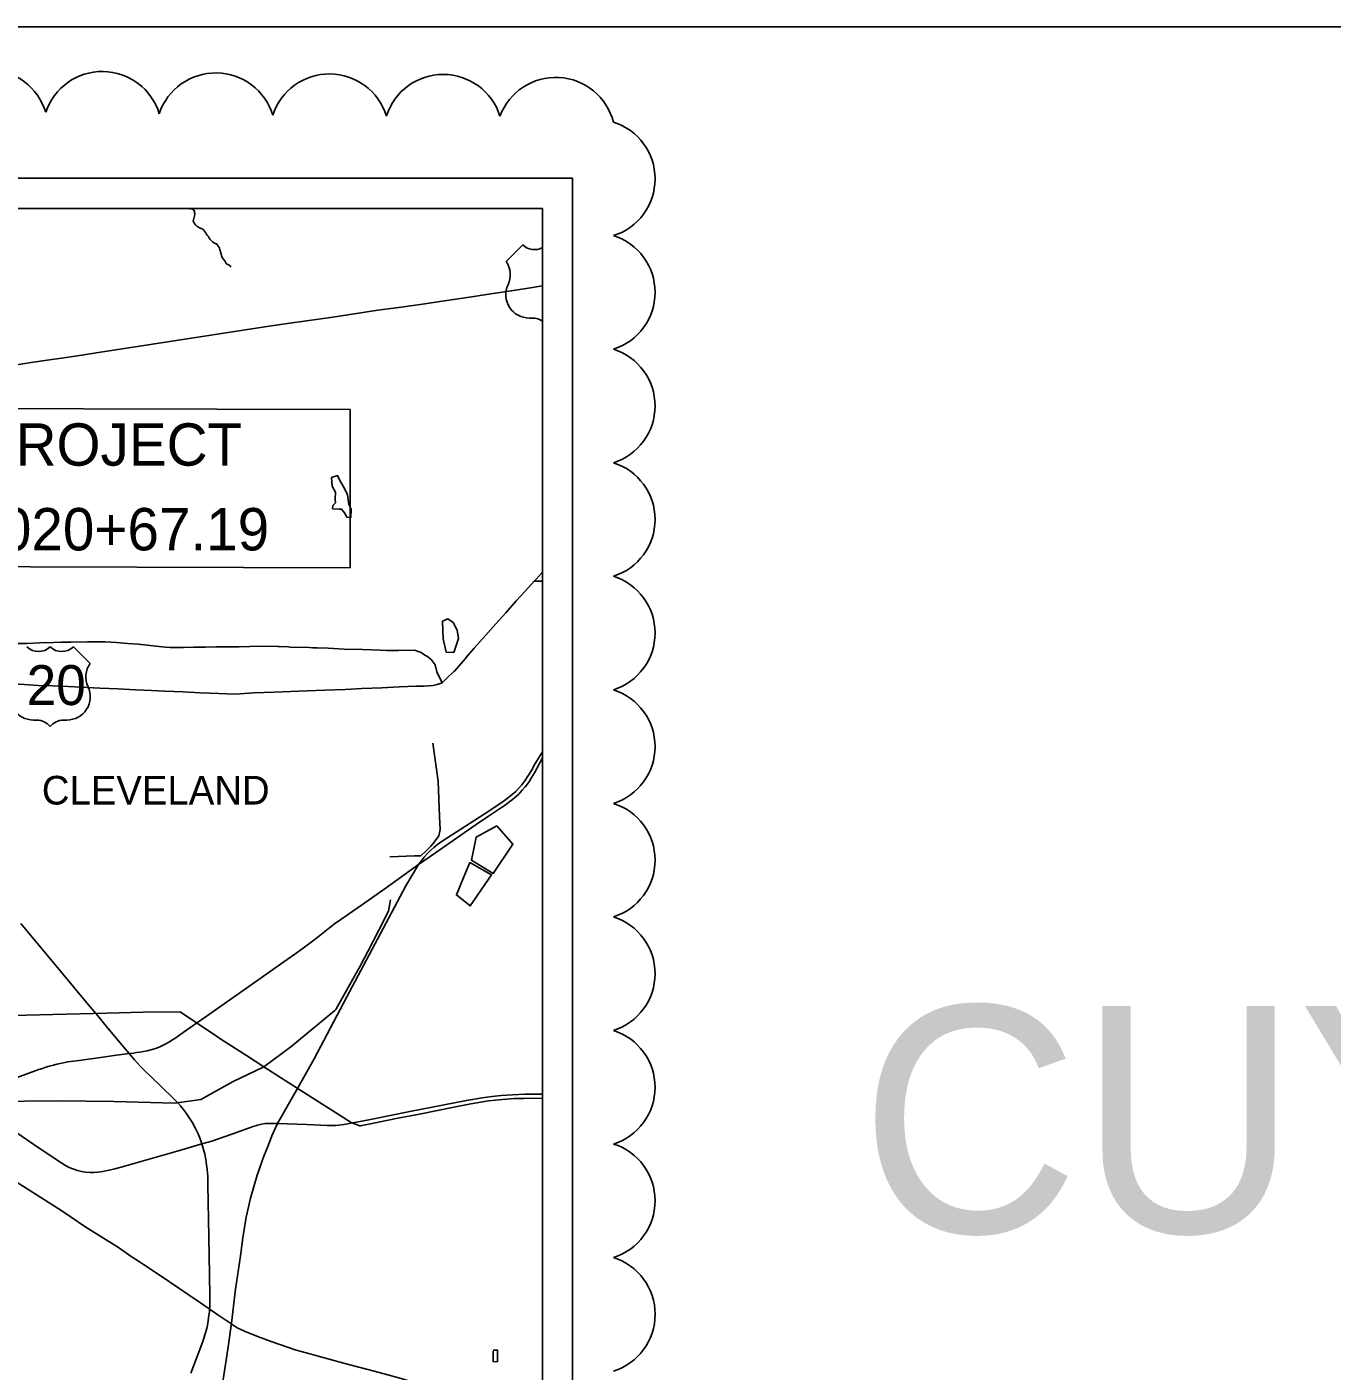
# Model space of a CAD drawing. Extents: x 0 to 96.2, y -27.5 to 31.3.
# Drawn here: x 48.919 to 53.234, y 16.942 to 21.387 of the extents above; entities that cross this region are included whole.
import ezdxf

# ---------------------------------------------------------------- set-up
doc = ezdxf.new("R2010")
doc.units = 0
for name, color, linetype in [('BOTTOM-BLKS', 7, 'Continuous'), ('DIM', 7, 'Continuous'), ('TB1', 7, 'Continuous'), ('TB_BORDER', 7, 'Continuous'), ('TB_PP_50x10', 7, 'Continuous'), ('TB_PP_50x10_GRID', 7, 'Continuous'), ('TB_PROF_30x10_GRID', 7, 'Continuous'), ('TB_PSDSOD', 7, 'Continuous'), ('TB_SIGN_XS', 7, 'Continuous'), ('TB_SUPER_50x0-5', 7, 'Continuous'), ('TB_SUPER_50x1', 7, 'Continuous'), ('TB_SUPER_50x1_GRID', 7, 'Continuous'), ('TB_UNDERDRAIN', 7, 'Continuous')]:
    doc.layers.add(name, color=color, linetype=linetype)

msp = doc.modelspace()

# ---------------------------------------------------------------- linework, layer by layer
at = {"layer": 'BOTTOM-BLKS'}
msp.add_lwpolyline([(43.8234, 18.3711), (43.8234, 13.9869), (50.6234, 13.9869), (50.6234, 20.7869), (47.5697, 20.7869)], dxfattribs=at)
at = {"layer": 'DIM'}
msp.add_lwpolyline([(43.2234, 21.3869), (74.7234, 21.3869), (74.7234, 0.3869), (43.2234, 0.3869)], close=True, dxfattribs=at)
at = {"layer": 'TB1'}
for p, q in [((43.7234, 20.8869), (50.7234, 20.8869)), ((50.7234, 20.8869), (50.7234, 13.8869)), ((43.8234, 20.7869), (50.6234, 20.7869)), ((50.6234, 20.7869), (50.6234, 13.9869))]:
    msp.add_line(p, q, dxfattribs=at)
at = {"layer": 'TB_BORDER'}
msp.add_lwpolyline([(49.4466, 20.7869), (49.4479, 20.7863), (49.4506, 20.7859), (49.4578, 20.7857), (49.4635, 20.7858), (49.4654, 20.7858), (49.4669, 20.7839), (49.4688, 20.7832), (49.4712, 20.7806), (49.4727, 20.7772), (49.4728, 20.7753), (49.4732, 20.7726), (49.474, 20.7688), (49.4748, 20.7669), (49.4737, 20.7623), (49.4719, 20.7577), (49.4705, 20.7528), (49.4694, 20.749), (49.469, 20.7471), (49.4691, 20.7448), (49.471, 20.741), (49.4737, 20.7369), (49.4765, 20.7323), (49.4788, 20.7305), (49.4811, 20.7282), (49.4834, 20.7267), (49.4865, 20.7249), (49.4903, 20.723), (49.4987, 20.7194), (49.5006, 20.7179), (49.5026, 20.7156), (49.5065, 20.7111), (49.5096, 20.707), (49.5123, 20.7028), (49.5154, 20.6983), (49.5181, 20.6946), (49.5205, 20.6908), (49.522, 20.6882), (49.5236, 20.6859), (49.5251, 20.684), (49.529, 20.6795), (49.5328, 20.6762), (49.5355, 20.6743), (49.5375, 20.6728), (49.5401, 20.6713), (49.5436, 20.6699), (49.5466, 20.6691), (49.5494, 20.6654), (49.5517, 20.6624), (49.5536, 20.6601), (49.5556, 20.6552), (49.5572, 20.6499), (49.5588, 20.6438), (49.5604, 20.6389), (49.5612, 20.6355), (49.562, 20.6332), (49.5628, 20.6302), (49.5636, 20.6279), (49.5652, 20.6249), (49.5679, 20.6204), (49.573, 20.6129), (49.5742, 20.611), (49.5753, 20.6087), (49.5769, 20.6065), (49.5784, 20.6046), (49.58, 20.6027), (49.5834, 20.6012), (49.5857, 20.5998), (49.5888, 20.5979), (49.5942, 20.5936)], dxfattribs=at)
at = {"layer": 'TB_PP_50x10_GRID'}
for points in [[(50.2136, 18.6169), (50.2181, 18.6233), (50.2251, 18.6322), (50.2323, 18.6415), (50.2426, 18.6523), (50.2542, 18.6642), (50.2644, 18.6733), (50.2769, 18.6833), (50.2919, 18.6943), (50.4304, 18.7837), (50.4859, 18.8201), (50.5066, 18.8351), (50.5243, 18.8494), (50.535, 18.8588), (50.5443, 18.8686), (50.555, 18.8808), (50.5655, 18.8945), (50.5756, 18.9094), (50.5871, 18.9284), (50.5999, 18.9515), (50.6234, 18.9902)], [(50.2136, 18.6169), (50.2705, 18.6556), (50.3649, 18.722), (50.4045, 18.7496), (50.4451, 18.7775), (50.4879, 18.8053), (50.5004, 18.8139), (50.5117, 18.8219), (50.5202, 18.8284), (50.5298, 18.8362), (50.5379, 18.8436), (50.5453, 18.8504), (50.5569, 18.8627), (50.5663, 18.8738), (50.5731, 18.8822), (50.5802, 18.8926), (50.5864, 18.9025), (50.592, 18.9117), (50.5971, 18.9207), (50.6234, 18.97)], [(49.2578, 17.9919), (49.2711, 17.9937), (49.2818, 17.9952), (49.2924, 17.9969), (49.3041, 17.9988), (49.3169, 18.0014), (49.3286, 18.0044), (49.3406, 18.0079), (49.3508, 18.0116), (49.3634, 18.0168), (49.3759, 18.0228), (49.3881, 18.0295), (49.4004, 18.0372), (49.411, 18.0441), (49.4247, 18.0539), (49.4579, 18.0771), (49.5085, 18.1125), (49.6008, 18.1772), (49.6822, 18.2344), (49.7685, 18.2951), (49.8054, 18.321), (49.833, 18.3408), (49.8549, 18.3573), (49.8673, 18.3666), (49.8823, 18.3787), (49.9151, 18.4046), (49.9364, 18.4207), (49.957, 18.4354), (49.9824, 18.4533), (50.0249, 18.4831), (50.099, 18.535), (50.2136, 18.6169)], [(49.7478, 17.7613), (49.8147, 17.8786), (49.8688, 17.9749), (49.977, 18.1803), (50.1154, 18.4408), (50.1723, 18.5472), (50.2136, 18.6169)], [(48.8989, 18.4225), (49.0301, 18.2651), (49.116, 18.1615), (49.1534, 18.1165), (49.187, 18.0766), (49.2389, 18.0141), (49.2578, 17.9919)], [(48.321, 17.6924), (48.5615, 17.7814), (48.6387, 17.8158), (48.7384, 17.8526), (48.7641, 17.8612), (48.7995, 17.8782), (48.8425, 17.897), (48.8963, 17.9164), (48.9462, 17.9349), (48.9581, 17.939), (48.9707, 17.9432), (48.9821, 17.9469), (48.9938, 17.9505), (49.0068, 17.9538), (49.0185, 17.957), (49.0407, 17.9615), (49.0549, 17.9643), (49.092, 17.9697), (49.1628, 17.9795), (49.2154, 17.9866), (49.2578, 17.9919)], [(49.2578, 17.9919), (49.2753, 17.9716), (49.2952, 17.9494), (49.312, 17.9323), (49.3274, 17.9172), (49.3627, 17.8834), (49.4048, 17.8428), (49.4171, 17.8306), (49.4266, 17.8195), (49.436, 17.8082), (49.4456, 17.7954), (49.4548, 17.7823), (49.465, 17.7658), (49.4764, 17.7447), (49.4849, 17.7272), (49.4915, 17.7107), (49.498, 17.6935)], [(50.6234, 17.8582), (50.6179, 17.8582), (50.5655, 17.8577), (50.524, 17.856), (50.4867, 17.8535), (50.4572, 17.8506), (50.4244, 17.8462), (50.3722, 17.8375), (50.2981, 17.8225), (50.1855, 17.8003), (50.0554, 17.7744), (49.9798, 17.7593), (49.9674, 17.7573), (49.9507, 17.7551), (49.94, 17.7542), (49.9263, 17.7542), (49.912, 17.7542), (49.845, 17.7571), (49.7478, 17.7613)], [(49.7478, 17.7613), (49.7247, 17.7612), (49.7067, 17.7604), (49.6951, 17.7586), (49.6813, 17.7554), (49.6671, 17.7514), (49.6368, 17.7405), (49.6032, 17.7283), (49.568, 17.7155), (49.5465, 17.7077), (49.5309, 17.7027), (49.498, 17.6935)], [(49.5954, 17.1006), (49.6084, 17.2128), (49.6258, 17.3238), (49.6332, 17.3834), (49.6442, 17.4513), (49.6579, 17.5145), (49.6809, 17.5906), (49.7019, 17.653), (49.7175, 17.6906), (49.7285, 17.72), (49.7478, 17.7613)], [(49.498, 17.6935), (49.4316, 17.6744), (49.2307, 17.6163), (49.2102, 17.6107), (49.1912, 17.6064), (49.1698, 17.6024), (49.1541, 17.6001), (49.1399, 17.5992), (49.1281, 17.5992), (49.1133, 17.6004), (49.0998, 17.6025), (49.086, 17.6059), (49.0713, 17.6108), (49.0593, 17.6156), (49.0469, 17.6218), (49.0342, 17.6295), (48.9992, 17.653), (48.9418, 17.6919), (48.8855, 17.7301)], [(49.498, 17.6935), (49.502, 17.6785), (49.5069, 17.659), (49.5102, 17.6422), (49.513, 17.6241), (49.515, 17.6086), (49.517, 17.5863), (49.5177, 17.5587), (49.5201, 17.3849), (49.5223, 17.2604), (49.5237, 17.1885), (49.5237, 17.1614), (49.5225, 17.1397), (49.5199, 17.1185), (49.5168, 17.0991), (49.5136, 17.0829), (49.5078, 17.0623), (49.5019, 17.0431), (49.4944, 17.0226), (49.4818, 16.9902), (49.4608, 16.9356)], [(49.6742, 15.7073), (49.6719, 15.7355), (49.6647, 15.7911), (49.654, 15.8647), (49.6481, 15.9142), (49.6185, 16.1187), (49.5828, 16.3874), (49.5736, 16.447), (49.5653, 16.5012), (49.5553, 16.5644), (49.5516, 16.6213), (49.5507, 16.6727), (49.5534, 16.7295), (49.5553, 16.78), (49.5608, 16.8506), (49.5681, 16.9148), (49.5837, 17.0147), (49.5954, 17.1006)]]:
    msp.add_lwpolyline(points, dxfattribs=at)
at = {"layer": 'TB_PROF_30x10_GRID'}
for points in [[(50.119, 18.6432), (50.2002, 18.6456), (50.2217, 18.646), (50.2402, 18.664), (50.2543, 18.6777), (50.2624, 18.6873), (50.2689, 18.6955), (50.2806, 18.7125), (50.2852, 18.7334), (50.2832, 18.7758), (50.2786, 18.8933), (50.2612, 19.0184)], [(48.7979, 17.8332), (49.0235, 17.8357), (49.2068, 17.8333), (49.4078, 17.8283), (49.4946, 17.8407), (49.6012, 17.9002), (49.7004, 17.9473), (49.7024, 17.9487), (49.7922, 18.0142), (49.937, 18.1349), (49.9409, 18.1382), (50.0222, 18.2836), (50.0467, 18.3302), (50.0831, 18.4002), (50.1145, 18.463), (50.1211, 18.5004)]]:
    msp.add_lwpolyline(points, dxfattribs=at)
at = {"layer": 'TB_PSDSOD'}
for points in [[(48.2359, 18.1025), (48.8731, 18.1185), (49.1821, 18.1253), (49.3037, 18.129), (49.4261, 18.1302)], [(49.4261, 18.1302), (49.546, 18.0495), (49.5602, 18.0403)], [(49.5602, 18.0403), (49.645, 17.9856), (49.7024, 17.9487), (49.8126, 17.878), (49.9914, 17.7643), (50.0197, 17.7535)], [(50.0197, 17.7535), (50.0212, 17.7529), (50.0441, 17.7578), (50.145, 17.7781), (50.217, 17.7921), (50.3302, 17.8147), (50.3868, 17.8264), (50.4457, 17.8358), (50.4909, 17.8404), (50.5297, 17.8435), (50.5618, 17.8441), (50.6234, 17.8442)]]:
    msp.add_lwpolyline(points, dxfattribs=at)
at = {"layer": 'TB_SIGN_XS'}
for points in [[(48.8781, 20.2684), (48.9334, 20.2769), (48.986, 20.285), (49.041, 20.2927), (49.1008, 20.3012), (49.1413, 20.3077), (49.7204, 20.3977), (49.7886, 20.4072), (49.9303, 20.4268), (50.0798, 20.4506), (50.1568, 20.4602), (50.227, 20.4699), (50.3002, 20.4807), (50.3821, 20.4931), (50.4526, 20.5043), (50.5201, 20.5139), (50.5842, 20.5246), (50.6234, 20.5312)], [(50.5966, 19.554), (50.6029, 19.561), (50.6234, 19.5835)], [(50.3759, 19.3071), (50.398, 19.3327), (50.4348, 19.3743), (50.4698, 19.4133), (50.5025, 19.4493), (50.5364, 19.489), (50.568, 19.5227), (50.5966, 19.554)], [(50.5966, 19.554), (50.6234, 19.5542)], [(48.864, 19.3479), (48.9194, 19.3486), (48.9615, 19.3503), (49.0073, 19.3512), (49.0335, 19.352), (49.0642, 19.3527), (49.1199, 19.3538), (49.1579, 19.3538), (49.1783, 19.3534), (49.2159, 19.3512), (49.2512, 19.3486), (49.2873, 19.346), (49.318, 19.343), (49.3457, 19.3396), (49.3773, 19.3358), (49.3932, 19.3345), (49.4118, 19.3343), (49.4372, 19.335), (49.4713, 19.3355), (49.51, 19.3363), (49.5434, 19.3368), (49.5816, 19.3376), (49.6059, 19.3368), (49.6208, 19.3372), (49.6565, 19.3381), (49.7104, 19.3389), (49.7489, 19.3378)], [(49.7489, 19.3378), (49.7533, 19.3377), (49.7843, 19.3366), (49.7894, 19.3364), (49.8532, 19.3343), (49.8641, 19.3339), (49.8793, 19.3333)], [(49.8793, 19.3333), (49.9147, 19.3321), (49.9682, 19.3298), (50.0282, 19.328), (50.0871, 19.3258), (50.1077, 19.3252), (50.1131, 19.3253), (50.1471, 19.3247), (50.2003, 19.3256), (50.2192, 19.3192)], [(50.2192, 19.3192), (50.223, 19.318), (50.2319, 19.3122), (50.2446, 19.3036), (50.2559, 19.295), (50.2656, 19.2822)], [(50.3325, 19.2571), (50.3676, 19.2975), (50.3759, 19.3071)], [(50.2656, 19.2822), (50.2679, 19.2792), (50.2707, 19.2689), (50.2744, 19.2549), (50.2919, 19.2175)], [(50.2919, 19.2175), (50.3072, 19.2335), (50.3309, 19.2553), (50.3325, 19.2571)], [(48.7197, 19.2229), (48.72, 19.2229), (48.7462, 19.2211), (48.7671, 19.2206), (48.7978, 19.2191), (48.8507, 19.2161), (48.8532, 19.216), (48.9113, 19.2129), (48.9568, 19.2097), (49.0039, 19.208), (49.0555, 19.2056), (49.0961, 19.2035), (49.1606, 19.2001)], [(49.1606, 19.2001), (49.2201, 19.1978), (49.2786, 19.1948), (49.3309, 19.1924), (49.3753, 19.1903), (49.4345, 19.188), (49.4918, 19.1853), (49.554, 19.1827), (49.607, 19.1807), (49.6242, 19.1817), (49.668, 19.1844), (49.7367, 19.1868), (49.7902, 19.1891), (49.846, 19.1914), (49.9045, 19.1938), (49.9713, 19.1962), (50.0267, 19.1989), (50.092, 19.2012), (50.1107, 19.2022), (50.1111, 19.2022)], [(50.1111, 19.2022), (50.1504, 19.2043), (50.2054, 19.207), (50.2309, 19.2072), (50.2324, 19.2073)], [(50.2324, 19.2073), (50.2477, 19.2079), (50.262, 19.209), (50.276, 19.2125), (50.2919, 19.2175)], [(48.6791, 17.7011), (48.8954, 17.5607), (49.0347, 17.4719), (49.1144, 17.4183), (49.2215, 17.3514), (49.2641, 17.3207), (49.2909, 17.3034), (49.3043, 17.2947)], [(49.3043, 17.2947), (49.3566, 17.2608), (49.4898, 17.1701), (49.5507, 17.1287), (49.5969, 17.0971), (49.6142, 17.0855), (49.6383, 17.074), (49.6678, 17.0621), (49.6766, 17.0586)], [(49.6766, 17.0586), (49.6845, 17.0554), (49.7268, 17.0405), (49.8089, 17.0113)], [(49.8089, 17.0113), (49.8591, 16.9979), (49.8818, 16.9911), (49.9863, 16.9631), (50.0468, 16.9473), (50.1007, 16.9327), (50.156, 16.9178), (50.1776, 16.9117), (50.2231, 16.8998), (50.2753, 16.8858), (50.3291, 16.8722), (50.443, 16.8416), (50.5125, 16.8233), (50.5699, 16.8072), (50.6234, 16.7933)]]:
    msp.add_lwpolyline(points, dxfattribs=at)
at = {"layer": 'TB_SUPER_50x0-5'}
for p, q in [((50.5583, 20.666), (50.5034, 20.6111)), ((50.6234, 20.4139), (50.6234, 20.6572)), ((50.5803, 20.4243), (50.5913, 20.4243)), ((49.1279, 19.2819), (49.0729, 19.3368)), ((48.9411, 19.0951), (48.9521, 19.0951)), ((49.04, 19.0951), (49.051, 19.0951))]:
    msp.add_line(p, q, dxfattribs=at)
for centre, radius, start, end in [((50.5968, 20.7052), 0.0549, 225.573, 298.9873), ((50.4404, 20.567), 0.0769, 334.5471, 35.0009), ((50.5794, 20.5012), 0.0769, 154.8319, 270.6383), ((50.5913, 20.3694), 0.0549, 54.2241, 90), ((48.9576, 19.3761), 0.0549, 225.573, 314.427), ((49.0345, 19.3761), 0.0549, 225.573, 314.427), ((49.1909, 19.2378), 0.0769, 144.9991, 205.4529), ((48.9403, 19.172), 0.0769, 154.8319, 270.6383), ((49.0518, 19.172), 0.0769, 269.3617, 25.1681), ((48.9521, 19.0402), 0.0549, 36.8699, 90), ((49.04, 19.0402), 0.0549, 90, 143.1301)]:
    msp.add_arc(centre, radius, start, end, dxfattribs=at)
at = {"layer": 'TB_SUPER_50x1'}
msp.add_lwpolyline([(48.2252, 20.1261), (49.9878, 20.1215), (49.9878, 19.5988), (48.2252, 19.6035)], close=True, dxfattribs=at)
at = {"layer": 'TB_SUPER_50x1_GRID'}
for centre, radius, start, end in [((48.7928, 21.0481), 0.1968, 16.6373, 161.6373), ((49.1683, 21.0427), 0.1968, 16.728, 161.728), ((49.5438, 21.0381), 0.1968, 16.8557, 161.8557), ((49.9194, 21.0345), 0.1968, 17.0555, 162.0555), ((50.2953, 21.0329), 0.1968, 17.4416, 162.4416), ((50.6675, 21.0228), 0.197, 14.4743, 159.4743), ((50.7991, 20.8844), 0.1968, 287.5, 72.5), ((50.799, 20.509), 0.1969, 287.5, 72.5), ((50.799, 20.1335), 0.1968, 287.5, 72.5), ((50.799, 19.7581), 0.1968, 287.5, 72.5), ((50.799, 19.3826), 0.1968, 287.5, 72.5), ((50.799, 19.0072), 0.1968, 287.5, 72.5), ((50.799, 18.6317), 0.1968, 287.5, 72.5), ((50.799, 18.2563), 0.1968, 287.5, 72.5), ((50.799, 17.8808), 0.1968, 287.5, 72.5), ((50.7991, 17.5054), 0.1968, 287.503, 72.503), ((50.7992, 17.1299), 0.1968, 287.5268, 72.5268)]:
    msp.add_arc(centre, radius, start, end, dxfattribs=at)
at = {"layer": 'TB_UNDERDRAIN'}
for points in [[(49.9605, 19.8757), (49.9539, 19.8875), (49.946, 19.9033), (49.9263, 19.8972)], [(49.9263, 19.8972), (49.9284, 19.8684), (49.9395, 19.8484), (49.9381, 19.824), (49.9391, 19.813), (49.9309, 19.8049), (49.9296, 19.7938), (49.952, 19.7923), (49.9597, 19.7917), (49.969, 19.7805), (49.9766, 19.7658), (49.9899, 19.7642), (49.9908, 19.792), (49.9833, 19.8078), (49.9785, 19.8393), (49.9693, 19.8608), (49.9605, 19.8757)], [(50.294, 19.3915), (50.2951, 19.363), (50.3055, 19.3198), (50.3302, 19.3188), (50.3464, 19.3648), (50.3413, 19.3924), (50.3279, 19.4173), (50.3112, 19.4295), (50.2928, 19.4223)], [(50.2928, 19.4223), (50.294, 19.3915)], [(50.4015, 18.6917), (50.3893, 18.6314), (50.4611, 18.5879), (50.5257, 18.6848), (50.4726, 18.7456)], [(50.4726, 18.7456), (50.4048, 18.7081), (50.4015, 18.6917)], [(50.3637, 18.5766), (50.339, 18.5169), (50.3849, 18.4803), (50.4555, 18.5829), (50.3833, 18.6239)], [(50.3833, 18.6239), (50.3637, 18.5766)], [(50.4605, 17.0115), (50.475, 17.0117), (50.4744, 16.9733), (50.4604, 16.9739), (50.4602, 17.0085), (50.4602, 17.0085)]]:
    msp.add_lwpolyline(points, dxfattribs=at)

# ---------------------------------------------------------------- texts
at = {"layer": 'TB1'}
msp.add_text('CUY-490-1.00 PART 2', height=0.75, dxfattribs=at).set_placement((51.6732, 17.3999))
at = {"layer": 'TB_PP_50x10'}
msp.add_text('CLEVELAND', height=0.0947, rotation=0, dxfattribs=at).set_placement((48.9685, 18.8157))
at = {"layer": 'TB_SUPER_50x0-5'}
msp.add_text('20', height=0.13184, dxfattribs=at).set_placement((48.9181, 19.1446))
at = {"layer": 'TB_SUPER_50x1'}
for s, p in [('END PROJECT', (48.3097, 19.936)), ('STA 1020+67.19', (48.3097, 19.656))]:
    msp.add_text(s, height=0.14, dxfattribs=at).set_placement(p)

doc.saveas('drawing.dxf')
